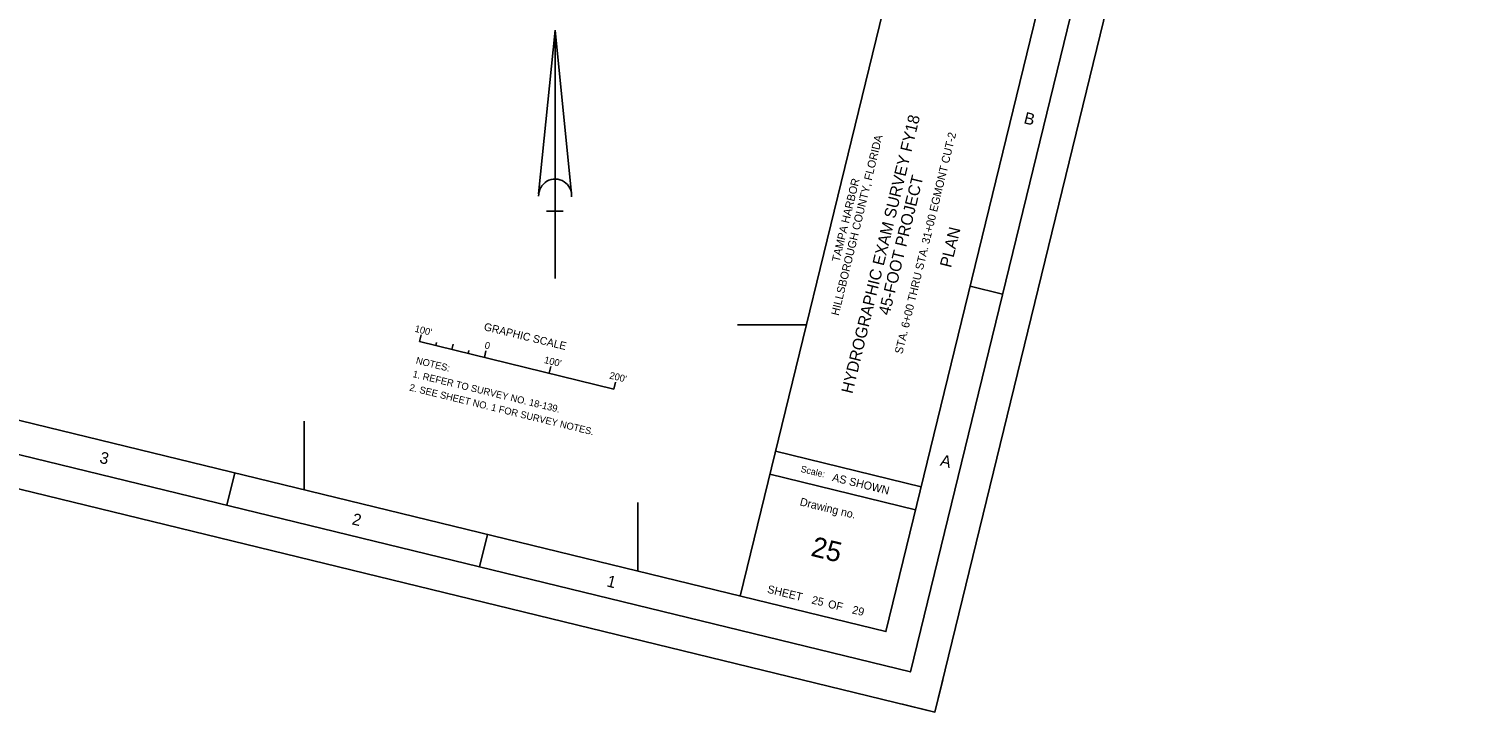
# Model space of a CAD drawing. Extents: x 403671 to 408751, y 1189919 to 1194265.
# Drawn here: x 406587 to 408751, y 1189919 to 1190944 of the extents above; entities that cross this region are included whole.
import ezdxf

# ---------------------------------------------------------------- set-up
doc = ezdxf.new("R2010")
doc.units = 0
for name, color, linetype in [('G-ANNO-NPLT', 7, 'Continuous'), ('G-ANNO-TEXT-DRWG', 7, 'Continuous'), ('G-ANNO-TEXT-PROJ', 7, 'Continuous'), ('G-ANNO-TEXT-TTLB', 7, 'Continuous'), ('G-ANNO-TTLB', 7, 'Continuous'), ('V-ANNO-NOTE', 7, 'Continuous'), ('V-ANNO-SYMB', 7, 'Continuous'), ('V-TOPO-COOR-STAT', 7, 'Continuous')]:
    doc.layers.add(name, color=color, linetype=linetype)

msp = doc.modelspace()

# ---------------------------------------------------------------- linework, layer by layer
at = {"layer": 'G-ANNO-NPLT'}
msp.add_lwpolyline([(404476.5, 1194264.7), (408751.2, 1193222.2), (407945.6, 1189919), (403670.9, 1190961.5)], close=True, dxfattribs=at)
msp.add_lwpolyline([(407957.4, 1189967.6), (407945.6, 1189919), (407897, 1189930.9)], dxfattribs=at)
at = {"layer": 'G-ANNO-TTLB'}
for p, q in [((408411.7, 1193202), (407653.5, 1190093.2)), ((408047.1, 1190546.1), (407998.5, 1190558)), ((407706.5, 1190310.6), (407925.2, 1190257.2)), ((406883.9, 1190229.4), (406895.8, 1190278)), ((407698.1, 1190275.9), (407916.7, 1190222.6)), ((407262.8, 1190137), (407274.7, 1190185.6))]:
    msp.add_line(p, q, dxfattribs=at)
for points in [[(403731.3, 1190998.2), (407908.9, 1189979.4), (408690.7, 1193185.4), (404513.2, 1194204.2)], [(408630.3, 1193148.7), (404622.8, 1194126), (403864.6, 1191017.2), (407872.1, 1190039.9)]]:
    msp.add_lwpolyline(points, close=True, dxfattribs=at)
at = {"layer": 'V-ANNO-NOTE'}
for p, q in [((407172.8, 1190474.9), (407175.3, 1190485)), ((407172.8, 1190474.9), (407464.3, 1190403.8)), ((407197.1, 1190468.9), (407198.2, 1190473.6)), ((407221.4, 1190463), (407223.4, 1190471.3)), ((407245.7, 1190457.1), (407246.8, 1190461.7)), ((407270, 1190451.2), (407272.4, 1190461.3)), ((407270, 1190451.2), (407272.4, 1190461.3)), ((407270, 1190451.2), (407271.2, 1190456)), ((407367.1, 1190427.5), (407369.6, 1190437.6)), ((407464.3, 1190403.8), (407466.7, 1190413.9))]:
    msp.add_line(p, q, dxfattribs=at)
at = {"layer": 'V-ANNO-SYMB'}
for p, q in [((407351.4, 1190696.5), (407376.1, 1190942.3)), ((407376.1, 1190569.9), (407376.1, 1190942.3)), ((407400.8, 1190696.5), (407376.1, 1190942.3)), ((407387.9, 1190670.5), (407363, 1190670.5))]:
    msp.add_line(p, q, dxfattribs=at)
msp.add_arc((407376.1, 1190694), 24.8, 355.2984, 182.0673, dxfattribs=at)
at = {"layer": 'V-TOPO-COOR-STAT'}
for p, q in [((407649.8, 1190500), (407752.7, 1190500)), ((407000, 1190252.5), (407000, 1190355.5)), ((407500, 1190130.6), (407500, 1190233.5))]:
    msp.add_line(p, q, dxfattribs=at)

# ---------------------------------------------------------------- texts
at = {"layer": 'G-ANNO-TEXT-DRWG'}
for s, height, rotation, p in [('STA. 6+00 THRU STA. 31+00 EGMONT CUT-2', 12, 76.2946, (407896.7, 1190455.6)), ('PLAN', 17.5, 76.2946, (407969.7, 1190585)), ('25', 30, 346.2946, (407758.2, 1190153.9)), (' 25          29', 12, 346.2946, (407755.6, 1190083.2))]:
    msp.add_text(s, height=height, rotation=rotation, dxfattribs=at).set_placement(p)
at = {"layer": 'G-ANNO-TEXT-PROJ'}
for s, height, p in [('HYDROGRAPHIC EXAM SURVEY FY18', 17.5, (407821.8, 1190395.9)), ('HILLSBOROUGH COUNTY, FLORIDA', 12, (407801.3, 1190513.2)), ('TAMPA HARBOR', 12, (407802.4, 1190593.6)), ('45-FOOT PROJECT', 17.5, (407877.5, 1190513.6))]:
    msp.add_text(s, height=height, rotation=76.2946, dxfattribs=at).set_placement(p)
at = {"layer": 'G-ANNO-TEXT-TTLB'}
for s, height, p in [('Scale:', 10, (407743.4, 1190279.6)), ('AS SHOWN', 12, (407790.8, 1190266)), ('Drawing no.', 12, (407742.2, 1190229.4)), ('SHEET         OF', 12, (407693.4, 1190098.3))]:
    msp.add_text(s, height=height, rotation=346.2946, dxfattribs=at).set_placement(p)
at = {"layer": 'G-ANNO-TTLB'}
for s, p in [('B', (408077.8, 1190802.8)), ('3', (406691.8, 1190293.4)), ('A', (407952.5, 1190289.1)), ('2', (407070.4, 1190201)), ('1', (407452.4, 1190107.9))]:
    msp.add_text(s, height=17.5, rotation=346.2946, dxfattribs=at).set_placement(p)
at = {"layer": 'V-ANNO-NOTE'}
for s, height, p in [("100'", 10.42, (407164.8, 1190489.9)), ('GRAPHIC SCALE', 11.666, (407268.5, 1190492.2)), ('0', 10.4, (407269.6, 1190465.1)), ('NOTES:', 10.42, (407166.6, 1190442.1)), ("100'", 10.42, (407358.9, 1190443)), ('1. REFER TO SURVEY NO. 18-139.', 10.416, (407161.7, 1190421.9)), ("200'", 10.42, (407456.7, 1190419.7)), ('2. SEE SHEET NO. 1 FOR SURVEY NOTES.', 10.416, (407156.8, 1190401.7))]:
    msp.add_text(s, height=height, rotation=346.2946, dxfattribs=at).set_placement(p)

doc.saveas('drawing.dxf')
